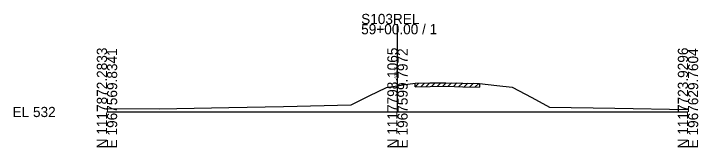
# Model space of a CAD drawing. Extents: x -26 to 163, y -10 to 24518.
# Drawn here: x -25.7 to 162.8, y 9490.3 to 9527 of the extents above; entities that cross this region are included whole.
import ezdxf

# ---------------------------------------------------------------- set-up
doc = ezdxf.new("R2010")
doc.units = 0
for name, color, linetype in [('RD_GPK_XS_Cell', 7, 'Continuous'), ('RD_XS_ExGround', 7, 'Continuous'), ('RD_XS_ExPaveRet', 7, 'Continuous'), ('RD_XS_TX_Elev_EX', 7, 'Continuous')]:
    doc.layers.add(name, color=color, linetype=linetype)

msp = doc.modelspace()

# ---------------------------------------------------------------- linework, layer by layer
at = {"layer": 'RD_GPK_XS_Cell'}
for p, q in [((80, 9500), (80, 9524.15)), ((0, 9500), (80, 9500)), ((80, 9500), (160, 9500))]:
    msp.add_line(p, q, dxfattribs=at)
at = {"layer": 'RD_XS_ExGround'}
msp.add_lwpolyline([(0, 9501), (14.45, 9500.9), (33.59, 9501.21), (48.58, 9501.55), (67.21, 9501.97), (72.19, 9504.42), (76.94, 9506.73), (80, 9507.21), (81.43, 9507.43), (84.9, 9507.93), (89.02, 9507.99), (93.28, 9508.05), (98.03, 9507.95), (102.61, 9507.86), (107.33, 9507.3), (111.62, 9506.85), (116.96, 9503.96), (121.83, 9501.31), (139.81, 9501.09), (160, 9500.69)], dxfattribs=at)
at = {"layer": 'RD_XS_ExPaveRet'}
for p, q in [((84.9, 9506.93), (85.92, 9507.94)), ((84.9, 9506.93), (84.9, 9507.93)), ((86.4, 9506.95), (87.42, 9507.96)), ((87.9, 9506.97), (88.92, 9507.99)), ((89.4, 9506.99), (90.42, 9508.01)), ((90.9, 9507.02), (91.92, 9508.03)), ((92.4, 9507.04), (93.41, 9508.05)), ((93.9, 9507.04), (94.88, 9508.02)), ((95.4, 9507), (96.38, 9507.98)), ((96.9, 9506.97), (97.88, 9507.95)), ((98.4, 9506.94), (99.39, 9507.92)), ((99.9, 9506.91), (100.89, 9507.9)), ((101.4, 9506.89), (102.39, 9507.87)), ((102.61, 9507.86), (102.61, 9506.86)), ((84.9, 9506.93), (89.02, 9506.99)), ((89.02, 9506.99), (93.28, 9507.05)), ((93.28, 9507.05), (98.03, 9506.95)), ((98.03, 9506.95), (102.61, 9506.86))]:
    msp.add_line(p, q, dxfattribs=at)

# ---------------------------------------------------------------- texts
at = {"layer": 'RD_GPK_XS_Cell'}
for s, p in [('S103REL', (70, 9524.15)), ('59+00.00 / 1', (70, 9521.35)), ('EL 532', (-26, 9498.6))]:
    msp.add_text(s, height=2.8, dxfattribs=at).set_placement(p)
for s, p in [('N 1117872.2833', (0, 9490)), ('E 1967569.8341', (2.8, 9490)), ('N 1117798.1065', (80, 9490)), ('E 1967599.7972', (82.8, 9490)), ('N 1117723.9296', (160, 9490)), ('E 1967629.7604', (162.8, 9490))]:
    msp.add_text(s, height=2.8, rotation=90, dxfattribs=at).set_placement(p)
at = {"layer": 'RD_XS_TX_Elev_EX'}
msp.add_text('539.21', height=0.8, rotation=90, dxfattribs=at).set_placement((79.9, 9509.21))

doc.saveas('drawing.dxf')
